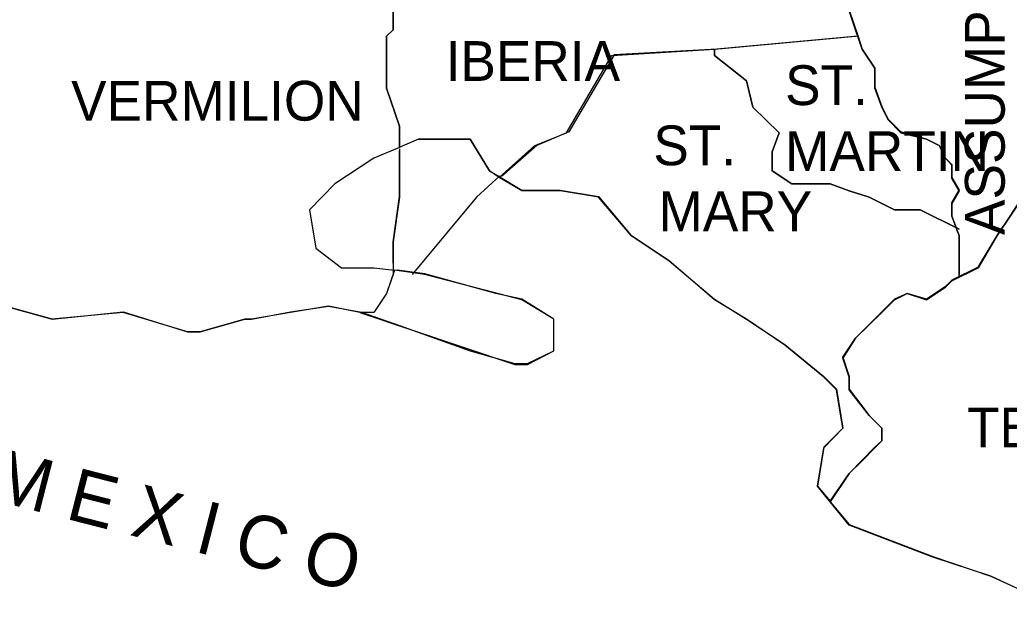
# Model space of a CAD drawing. Extents: x 0.19 to 2.82, y 0.04 to 1.79.
# Drawn here: x 2.3204 to 2.4368, y 1.4216 to 1.4916 of the extents above; entities that cross this region are included whole.
import ezdxf

# ---------------------------------------------------------------- set-up
doc = ezdxf.new("R2010")
doc.units = 0
for name, color, linetype in [('Dist02', 7, 'Continuous'), ('Dist03', 7, 'Continuous'), ('Dist61', 7, 'Continuous'), ('Standard Info', 7, 'Continuous')]:
    doc.layers.add(name, color=color, linetype=linetype)

msp = doc.modelspace()

# ---------------------------------------------------------------- linework, layer by layer
at = {"layer": 'Dist02'}
for points in [[(2.4369, 1.4685), (2.4354, 1.46625), (2.43315, 1.4625), (2.43007, 1.461), (2.42932, 1.46025), (2.42707, 1.45875), (2.42482, 1.45942), (2.42332, 1.45875), (2.42182, 1.45725), (2.41874, 1.45417), (2.41724, 1.45192), (2.41799, 1.44967), (2.41799, 1.44817), (2.42032, 1.44508), (2.42182, 1.44358), (2.42182, 1.44208), (2.42099, 1.44133), (2.41949, 1.43983), (2.41799, 1.43825), (2.41574, 1.43492)], [(2.41574, 1.43492), (2.41799, 1.43225), (2.42782, 1.4285), (2.43465, 1.42617), (2.44449, 1.42167), (2.44749, 1.42167), (2.45432, 1.42242), (2.45582, 1.42317), (2.46115, 1.42542), (2.46415, 1.42767), (2.46715, 1.4315), (2.4709, 1.43375), (2.47699, 1.43825), (2.47924, 1.43825), (2.48424, 1.43633)]]:
    msp.add_lwpolyline(points, dxfattribs=at)
at = {"layer": 'Dist03'}
for points in [[(2.41899, 1.48975), (2.41799, 1.49275), (2.41949, 1.495), (2.41799, 1.495), (2.41649, 1.49725), (2.40974, 1.49725)], [(2.43057, 1.46717), (2.43007, 1.4685), (2.43007, 1.47008), (2.4309, 1.47158), (2.43007, 1.47308), (2.43007, 1.47458), (2.42932, 1.47533), (2.42857, 1.47683), (2.42707, 1.47758), (2.42407, 1.47842), (2.42257, 1.47992), (2.42182, 1.48142), (2.42099, 1.48367), (2.42099, 1.48592), (2.41949, 1.48817), (2.41899, 1.48975)], [(2.36732, 1.47758), (2.3734, 1.47758), (2.37565, 1.47383), (2.37682, 1.47317)], [(2.36432, 1.463), (2.36432, 1.4655), (2.36507, 1.47083), (2.36507, 1.47608), (2.36507, 1.47625)], [(2.37682, 1.47317), (2.37949, 1.47158), (2.38399, 1.47158), (2.38849, 1.47083), (2.39232, 1.46625), (2.39682, 1.46325), (2.40215, 1.45875), (2.4059, 1.45642), (2.4104, 1.45342), (2.41499, 1.44967), (2.41649, 1.44817), (2.41724, 1.44358), (2.41499, 1.44133), (2.41424, 1.43675), (2.41574, 1.435)], [(2.4309, 1.46175), (2.4309, 1.46325), (2.4309, 1.46475), (2.4309, 1.46625), (2.43065, 1.46692)], [(2.36049, 1.45725), (2.36507, 1.45567), (2.3734, 1.45267), (2.37865, 1.45117), (2.38015, 1.45117), (2.38324, 1.45267), (2.38324, 1.45642), (2.37949, 1.45875), (2.3764, 1.45942), (2.36807, 1.46175), (2.36482, 1.46217)], [(2.41574, 1.435), (2.41799, 1.43825), (2.41949, 1.43983), (2.42099, 1.44133), (2.42182, 1.44208), (2.42182, 1.44358), (2.42032, 1.44508), (2.41799, 1.44817), (2.41799, 1.44967), (2.41724, 1.45192), (2.41874, 1.45417), (2.42182, 1.45725), (2.42332, 1.45875), (2.42482, 1.45942), (2.42707, 1.45875), (2.42932, 1.46025), (2.43007, 1.461), (2.43099, 1.46142)], [(2.31815, 1.45808), (2.32424, 1.45642), (2.33257, 1.45725), (2.34015, 1.45492), (2.34165, 1.45492), (2.3469, 1.45642), (2.34765, 1.45642)], [(2.34765, 1.45642), (2.35224, 1.45725), (2.35674, 1.45792), (2.3604, 1.45725)]]:
    msp.add_lwpolyline(points, dxfattribs=at)
at = {"layer": 'Dist61'}
for points in [[(2.40974, 1.49725), (2.41649, 1.49725), (2.41799, 1.495), (2.41949, 1.495), (2.41799, 1.49275), (2.41899, 1.48975)], [(2.41899, 1.48975), (2.41949, 1.48817), (2.42099, 1.48592), (2.42099, 1.48367), (2.42182, 1.48142), (2.42257, 1.47992), (2.42407, 1.47842), (2.42707, 1.47758), (2.42857, 1.47683), (2.42932, 1.47533), (2.43007, 1.47458), (2.43007, 1.47308), (2.4309, 1.47158), (2.43007, 1.47008), (2.43007, 1.4685), (2.43057, 1.46717)], [(2.4309, 1.46133), (2.43315, 1.4625), (2.4354, 1.46625), (2.4369, 1.4685), (2.4384, 1.47083), (2.44065, 1.47458), (2.44215, 1.47683), (2.44215, 1.47908), (2.44299, 1.48067), (2.44524, 1.48292)], [(2.43065, 1.46692), (2.4309, 1.46625), (2.4309, 1.46475), (2.4309, 1.46325), (2.4309, 1.46175)]]:
    msp.add_lwpolyline(points, dxfattribs=at)
at = {"layer": 'Standard Info'}
for p, q in [((2.3654, 1.47675), (2.36507, 1.47658)), ((2.43057, 1.46717), (2.4309, 1.467)), ((2.4309, 1.46133), (2.4309, 1.46175))]:
    msp.add_line(p, q, dxfattribs=at)
for points in [[(2.36507, 1.47658), (2.36507, 1.47908), (2.36357, 1.48358), (2.36357, 1.48967), (2.36432, 1.49042), (2.36432, 1.4935), (2.36507, 1.49575), (2.3654, 1.49725)], [(2.40974, 1.49725), (2.41649, 1.49725), (2.41799, 1.495), (2.41949, 1.495), (2.41799, 1.49267), (2.41899, 1.48967)], [(2.36457, 1.49408), (2.36432, 1.4935), (2.36432, 1.49042), (2.36357, 1.48967), (2.36357, 1.48358), (2.36507, 1.47908), (2.36507, 1.47658)], [(2.4309, 1.46175), (2.4309, 1.46475), (2.4309, 1.46625), (2.43007, 1.4685), (2.43007, 1.47), (2.4309, 1.4715), (2.43007, 1.473), (2.43007, 1.4745), (2.42932, 1.47533), (2.42857, 1.47683), (2.42707, 1.47758), (2.42407, 1.47833), (2.42257, 1.47983), (2.42182, 1.48133), (2.42099, 1.48358), (2.42099, 1.48592), (2.41949, 1.48817), (2.41874, 1.49042), (2.41799, 1.49267), (2.41849, 1.49333)], [(2.41899, 1.48967), (2.4024, 1.48817), (2.39032, 1.4875), (2.38499, 1.47842), (2.38124, 1.47683), (2.37707, 1.47317)], [(2.40215, 1.48817), (2.41874, 1.48967)], [(2.41899, 1.48975), (2.41949, 1.48817), (2.42099, 1.48592), (2.42099, 1.48358), (2.42182, 1.48133), (2.42257, 1.47983), (2.42407, 1.47833), (2.42707, 1.47758), (2.42857, 1.47683), (2.42932, 1.47533), (2.43007, 1.4745), (2.43007, 1.473), (2.4309, 1.4715), (2.43007, 1.47), (2.43007, 1.4685), (2.43057, 1.46717)], [(2.37682, 1.47308), (2.38099, 1.47683), (2.38474, 1.47833), (2.39007, 1.48742), (2.40215, 1.48817)], [(2.40215, 1.48817), (2.40215, 1.48742), (2.4059, 1.48442), (2.40665, 1.48133), (2.40974, 1.47833), (2.4089, 1.47608), (2.4089, 1.47383), (2.41124, 1.47233), (2.41274, 1.47233), (2.41574, 1.47233), (2.41799, 1.4715), (2.42032, 1.47075), (2.42182, 1.47), (2.42332, 1.46925), (2.42632, 1.46925), (2.4309, 1.467)], [(2.4309, 1.467), (2.42632, 1.46925), (2.42332, 1.46925), (2.42182, 1.47), (2.42032, 1.47075), (2.41799, 1.4715), (2.41574, 1.47233), (2.41274, 1.47233), (2.41124, 1.47233), (2.4089, 1.47383), (2.4089, 1.47608), (2.40974, 1.47833), (2.40665, 1.48133), (2.4059, 1.48442), (2.40215, 1.48742), (2.40215, 1.48817)], [(2.44524, 1.48283), (2.44299, 1.48058), (2.44215, 1.47908), (2.44215, 1.47683), (2.44065, 1.4745), (2.4384, 1.47075), (2.4369, 1.4685), (2.4354, 1.46625), (2.43315, 1.46242), (2.4309, 1.46133)], [(2.36732, 1.47758), (2.3654, 1.47675)], [(2.36732, 1.47758), (2.3654, 1.47675)], [(2.37682, 1.47308), (2.37565, 1.47383), (2.3734, 1.47758), (2.36732, 1.47758)], [(2.37682, 1.47308), (2.37565, 1.47383), (2.3734, 1.47758), (2.36732, 1.47758)], [(2.36507, 1.47658), (2.36207, 1.47533), (2.35749, 1.47233), (2.35449, 1.46925), (2.35524, 1.46475), (2.35824, 1.46242), (2.36207, 1.46242), (2.36449, 1.46217)], [(2.36507, 1.47642), (2.36507, 1.47608), (2.36507, 1.47075), (2.36432, 1.4655), (2.36432, 1.46167), (2.36357, 1.45942), (2.36207, 1.45717), (2.3604, 1.45717)], [(2.3769, 1.47325), (2.37415, 1.47075), (2.36657, 1.46167)], [(2.41574, 1.43492), (2.41424, 1.43675), (2.41499, 1.44125), (2.41724, 1.44358), (2.41649, 1.44808), (2.41499, 1.44958), (2.4104, 1.45333), (2.4059, 1.45642), (2.40215, 1.45867), (2.39682, 1.46325), (2.39232, 1.46625), (2.38849, 1.47075), (2.38399, 1.4715), (2.37949, 1.4715), (2.37682, 1.47308)], [(2.41574, 1.43492), (2.41799, 1.43825), (2.41949, 1.43975), (2.42099, 1.44125), (2.42182, 1.44208), (2.42182, 1.44358), (2.42032, 1.44508), (2.41799, 1.44808), (2.41799, 1.44958), (2.41724, 1.45183), (2.41874, 1.45417), (2.42182, 1.45717), (2.42332, 1.45867), (2.42482, 1.45942), (2.42707, 1.45867), (2.42932, 1.46017), (2.43007, 1.46092), (2.43315, 1.46242), (2.4354, 1.46625), (2.4369, 1.4685)], [(2.43065, 1.46692), (2.4309, 1.46625), (2.4309, 1.46475), (2.4309, 1.46325), (2.4309, 1.46167)], [(2.3604, 1.45717), (2.37865, 1.45108), (2.38015, 1.45108), (2.38324, 1.45267), (2.38324, 1.45642), (2.37949, 1.45867), (2.36807, 1.46167), (2.36449, 1.46217)], [(2.36449, 1.46217), (2.36357, 1.45942), (2.36207, 1.45717), (2.36132, 1.45717)], [(2.43099, 1.46142), (2.43007, 1.46092), (2.42932, 1.46017), (2.42707, 1.45867), (2.42482, 1.45942), (2.42332, 1.45867), (2.42182, 1.45717), (2.41874, 1.45417), (2.41724, 1.45183), (2.41799, 1.44958), (2.41799, 1.44808), (2.42032, 1.44508), (2.42182, 1.44358), (2.42182, 1.44208), (2.42099, 1.44125), (2.41949, 1.43975), (2.41799, 1.43825), (2.41574, 1.43492)], [(2.34765, 1.45642), (2.3469, 1.45642), (2.34165, 1.45492), (2.34015, 1.45492), (2.33257, 1.45717), (2.32424, 1.45642), (2.31815, 1.45808)], [(2.3604, 1.45717), (2.35674, 1.45792), (2.35224, 1.45717), (2.34765, 1.45642)], [(2.48424, 1.43625), (2.47924, 1.43825), (2.47699, 1.43825), (2.4709, 1.43367), (2.46715, 1.43142), (2.46415, 1.42767), (2.46115, 1.42542), (2.45582, 1.42308), (2.45432, 1.42242), (2.44749, 1.42158), (2.44449, 1.42158), (2.43465, 1.42617), (2.42782, 1.42842), (2.41799, 1.43217), (2.41574, 1.43492)]]:
    msp.add_lwpolyline(points, dxfattribs=at)

# ---------------------------------------------------------------- texts
for s, height, rotation, p in [('ASSUMPTION', 0.004679, 90.01, (2.43628, 1.4663)), ('G U L F   O F   M E X I C O', 0.0062, 345.6507, (2.26182, 1.4493))]:
    msp.add_text(s, height=height, rotation=rotation, dxfattribs=at).set_placement(p)
for s, p in [('IBERIA', (2.37051, 1.48442)), ('ST.', (2.41044, 1.48158)), ('VERMILION', (2.32645, 1.47975)), ('ST.', (2.39494, 1.4745)), ('MARTIN', (2.41044, 1.47383)), ('MARY', (2.39555, 1.46675)), ('TERREBONNE', (2.43184, 1.44133))]:
    msp.add_text(s, height=0.004679, dxfattribs=at).set_placement(p)

doc.saveas('drawing.dxf')
